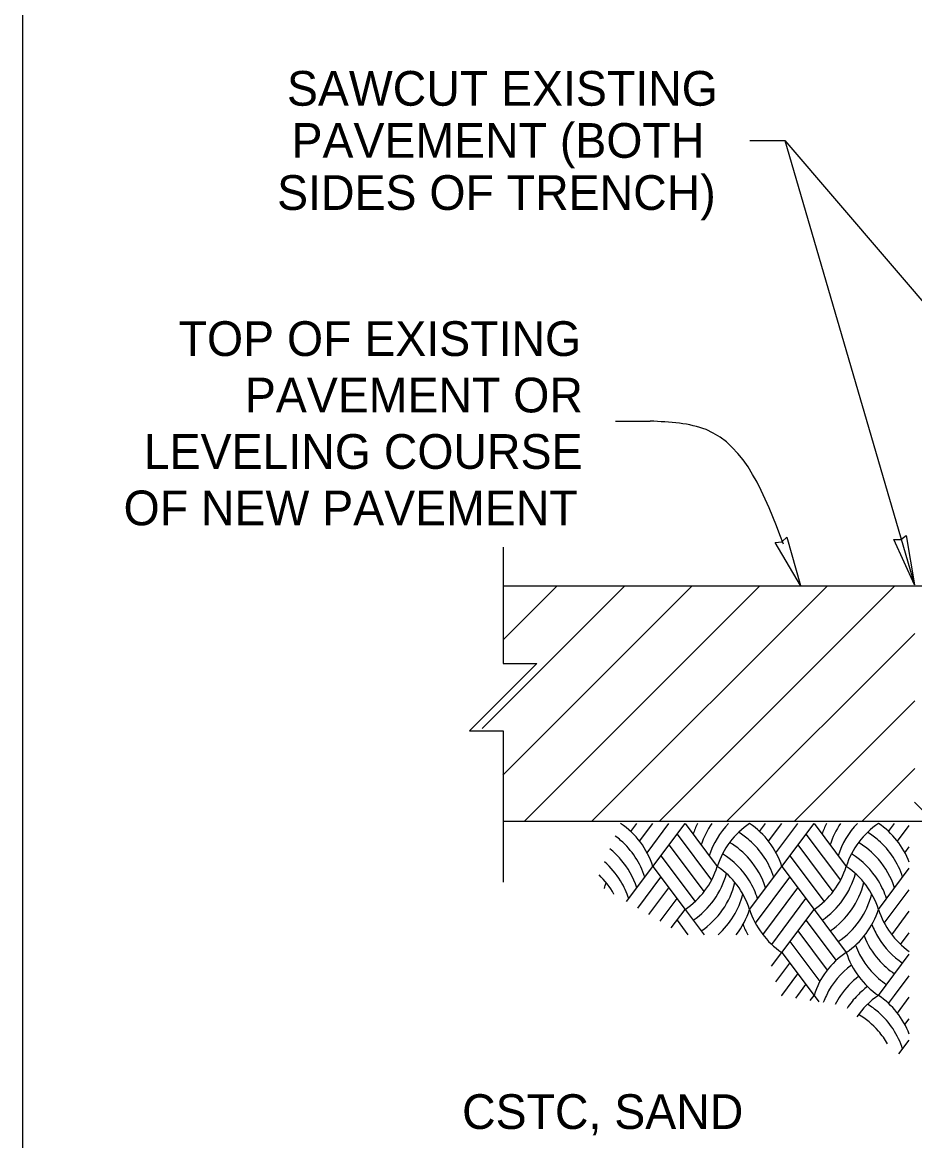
# Model space of a CAD drawing. Extents: x 99862 to 103151, y 100000 to 108153.
# Drawn here: x 99862 to 100273, y 100539 to 101054 of the extents above; entities that cross this region are included whole.
import ezdxf

# ---------------------------------------------------------------- set-up
doc = ezdxf.new("R2010")
doc.units = 0
for name, color, linetype in [('Level 1', 7, 'Continuous'), ('Level 10', 7, 'Continuous'), ('Level 15', 7, 'Continuous'), ('Level 18', 7, 'Continuous'), ('Level 20', 7, 'Continuous'), ('Level 27', 7, 'Continuous'), ('Level 60', 7, 'Continuous')]:
    doc.layers.add(name, color=color, linetype=linetype)

msp = doc.modelspace()

# ---------------------------------------------------------------- linework, layer by layer
at = {"layer": 'Level 1'}
msp.add_lwpolyline([(99862, 99999.5), (103151, 99999.5), (103151, 102075.5), (99862, 102075.5)], close=True, dxfattribs=at)
at = {"layer": 'Level 10'}
for points in [[(100406.95, 100794.33), (100083.51, 100794.33)], [(100582.64, 100685.87), (100083.51, 100685.87)]]:
    msp.add_lwpolyline(points, dxfattribs=at)
at = {"layer": 'Level 15'}
for p, q in [((100197.22, 100999.64), (100213.22, 100999.64)), ((100213.22, 100999.64), (100273.05, 100794.89)), ((100135.24, 100870.34), (100151.24, 100870.34))]:
    msp.add_line(p, q, dxfattribs=at)
for points in [[(100213.22, 100999.64), (100309.47, 100887.42)], [(100083.51, 100812.23), (100083.51, 100758.61), (100098.99, 100758.61), (100068.02, 100727.64), (100083.51, 100727.64), (100083.51, 100657.87)]]:
    msp.add_lwpolyline(points, dxfattribs=at)
for points in [[(100273.05, 100794.89), (100263.55, 100815.86), (100266.71, 100815.72), (100269.26, 100817.6)], [(100220.57, 100794.65), (100208.81, 100814.44), (100211.97, 100814.65), (100214.29, 100816.8)]]:
    msp.add_lwpolyline(points, close=True, dxfattribs=at)
msp.add_spline([(100212.64, 100813.62), (100177.01, 100866.4), (100151.24, 100870.34)], degree=3, dxfattribs=at)
at = {"layer": 'Level 27'}
msp.add_line((100280.56, 100687.2), (100272.99, 100694.77), dxfattribs=at)
at = {"layer": 'Level 60'}
for p, q in [((100073.79, 100728.73), (100139.39, 100794.33)), ((100083.35, 100707.18), (100170.51, 100794.33)), ((100083.51, 100769.56), (100108.28, 100794.33)), ((100093.16, 100685.87), (100201.62, 100794.33)), ((100124.27, 100685.87), (100232.73, 100794.33)), ((100155.38, 100685.87), (100263.84, 100794.33)), ((100186.49, 100685.87), (100273.15, 100772.53)), ((100217.61, 100685.87), (100273.15, 100741.41)), ((100248.72, 100685.87), (100273.15, 100710.3)), ((100142.3, 100681.27), (100145.07, 100684.96)), ((100146.37, 100676.81), (100152.49, 100684.96)), ((100149.82, 100671.5), (100159.92, 100684.96)), ((100152.49, 100665.17), (100167.34, 100684.96)), ((100167.34, 100684.96), (100182.19, 100665.17)), ((100201.69, 100681.27), (100204.46, 100684.96)), ((100205.77, 100676.81), (100211.89, 100684.96)), ((100209.21, 100671.5), (100219.31, 100684.96)), ((100211.89, 100665.17), (100226.74, 100684.96)), ((100226.74, 100684.96), (100241.59, 100665.17)), ((100261.09, 100681.27), (100263.86, 100684.96)), ((100265.17, 100676.81), (100270.63, 100684.09)), ((100163.63, 100680.01), (100179.52, 100658.83)), ((100223.03, 100680.01), (100238.91, 100658.83)), ((100159.92, 100675.07), (100176.07, 100653.52)), ((100219.31, 100675.07), (100235.47, 100653.52)), ((100268.61, 100671.5), (100270.63, 100674.19)), ((100156.2, 100670.12), (100172, 100649.06)), ((100215.6, 100670.12), (100231.39, 100649.06)), ((100140.38, 100649.02), (100152.49, 100665.17)), ((100152.49, 100665.17), (100167.34, 100645.37)), ((100197.04, 100645.37), (100211.89, 100665.17)), ((100211.89, 100665.17), (100226.74, 100645.37)), ((100256.44, 100645.37), (100270.63, 100664.29)), ((100145.53, 100645.99), (100156.2, 100660.22)), ((100199.71, 100639.03), (100215.6, 100660.22)), ((100150.69, 100642.96), (100159.92, 100655.27)), ((100203.16, 100633.72), (100219.31, 100655.27)), ((100259.11, 100639.03), (100270.63, 100654.39)), ((100155.85, 100639.94), (100163.63, 100650.32)), ((100207.23, 100629.26), (100223.03, 100650.32)), ((100161, 100636.91), (100167.34, 100645.37)), ((100167.34, 100645.37), (100176.09, 100633.7)), ((100211.89, 100625.57), (100226.74, 100645.37)), ((100226.74, 100645.37), (100241.59, 100625.57)), ((100262.55, 100633.72), (100270.63, 100644.49)), ((100163.63, 100640.42), (100168.67, 100633.7)), ((100223.03, 100640.42), (100236.93, 100621.87)), ((100219.31, 100635.47), (100232.86, 100617.41)), ((100266.63, 100629.26), (100270.63, 100634.59)), ((100215.6, 100630.52), (100229.41, 100612.1)), ((100207.1, 100619.18), (100211.89, 100625.57)), ((100211.89, 100625.57), (100226.74, 100605.77)), ((100256.44, 100605.77), (100270.63, 100624.69)), ((100209.1, 100611.95), (100215.6, 100620.62)), ((100211.89, 100605.77), (100219.31, 100615.67)), ((100263.86, 100605.77), (100270.63, 100614.79)), ((100219.31, 100605.77), (100223.03, 100610.72)), ((100211.76, 100605.6), (100211.89, 100605.77)), ((100218.38, 100604.53), (100219.31, 100605.77)), ((100225.01, 100603.46), (100226.74, 100605.77)), ((100226.74, 100605.77), (100228.95, 100602.83)), ((100261.09, 100602.07), (100263.86, 100605.77)), ((100265.17, 100597.61), (100270.63, 100604.89)), ((100268.61, 100592.3), (100270.63, 100594.99)), ((100265.89, 100578.78), (100270.63, 100585.09))]:
    msp.add_line(p, q, dxfattribs=at)
for centre, start, end in [((100116.68, 100653.78), 17.6434, 56.0957), ((100206.86, 100668.63), 154.2266, 162.3566), ((100210.58, 100663.68), 145.491, 162.3566), ((100214.29, 100658.73), 135.7127, 162.3566), ((100218, 100653.78), 123.9036, 162.3566), ((100176.08, 100653.78), 17.6434, 56.0963), ((100266.26, 100668.63), 154.2266, 162.3566), ((100269.97, 100663.68), 145.491, 162.3566), ((100273.68, 100658.73), 135.7127, 162.3566), ((100277.4, 100653.78), 123.9036, 162.3566), ((100235.47, 100653.78), 20.6916, 56.0963), ((100112.97, 100648.83), 48.9597, 53.7468), ((100172.37, 100648.83), 48.9597, 58.5465), ((100231.76, 100648.83), 48.9597, 58.5465), ((100109.26, 100643.88), 40.9413, 51.3732), ((100112.97, 100648.83), 17.6434, 48.9597), ((100168.66, 100643.88), 40.9413, 59.3021), ((100172.37, 100648.83), 17.6434, 48.9597), ((100228.05, 100643.88), 40.9413, 59.3021), ((100231.76, 100648.83), 17.6434, 48.9597), ((100109.26, 100643.88), 17.6434, 40.9414), ((100164.94, 100638.93), 31.3316, 58.4874), ((100168.65, 100643.88), 17.6434, 40.9414), ((100224.34, 100638.93), 31.3316, 58.4874), ((100228.05, 100643.88), 17.6434, 40.9414), ((100105.55, 100638.93), 31.3316, 48.9712), ((100146.38, 100676.55), 303.9036, 342.3566), ((100161.23, 100633.98), 17.6434, 56.0964), ((100205.78, 100676.55), 303.9036, 342.3566), ((100220.63, 100633.98), 17.6434, 56.0964), ((100101.83, 100633.98), 29.3994, 46.5357), ((100094.41, 100666.66), 341.9694, 346.3199), ((100105.55, 100638.93), 17.6434, 31.3317), ((100150.09, 100671.61), 303.9036, 345.0113), ((100153.81, 100666.66), 303.9036, 346.3199), ((100164.94, 100638.93), 17.6434, 31.3317), ((100209.49, 100671.61), 303.9036, 345.0113), ((100213.2, 100666.66), 303.9036, 346.3199), ((100224.34, 100638.93), 17.6434, 31.3317), ((100098.12, 100661.71), 345.7294, 345.7713), ((100157.52, 100661.71), 311.8163, 345.7713), ((100216.91, 100661.71), 303.9036, 345.7713), ((100161.23, 100656.76), 322.1523, 342.3566), ((100232.85, 100656.76), 197.6435, 236.0964), ((100220.63, 100656.76), 303.9036, 342.3566), ((100292.25, 100656.76), 197.6435, 234.8819), ((100229.14, 100651.81), 200.8778, 208.8059), ((100288.53, 100651.81), 200.8778, 211.332), ((100284.82, 100646.86), 201.4344, 220.9416), ((100288.53, 100651.81), 211.3319, 236.0964), ((100281.11, 100641.91), 200.2432, 228.9599), ((100262.55, 100594.38), 123.9036, 162.3566), ((100277.4, 100636.96), 197.6434, 236.0964), ((100284.82, 100646.86), 220.9415, 236.0964), ((100266.26, 100589.43), 126.3063, 154.2266), ((100269.97, 100584.48), 127.1006, 145.4911), ((100281.11, 100641.91), 228.9599, 236.0964), ((100273.68, 100579.53), 126.331, 135.7128), ((100266.26, 100589.43), 154.2265, 159.6619), ((100269.97, 100584.48), 145.491, 152.8911), ((100273.68, 100579.53), 135.7127, 147.4303), ((100277.4, 100574.58), 123.9036, 145.4797), ((100231.76, 100569.63), 48.9597, 58.5465), ((100235.47, 100574.58), 20.6916, 56.0963), ((100228.05, 100564.68), 40.9413, 59.3021), ((100231.76, 100569.63), 17.6434, 48.9597), ((100228.05, 100564.68), 29.8741, 40.9414)]:
    msp.add_arc(centre, 37.58, start, end, dxfattribs=at)

# ---------------------------------------------------------------- texts
at = {"layer": 'Level 18'}
for s, p in [('SAWCUT EXISTING', (99983.9, 101015.64)), ('PAVEMENT (BOTH ', (99986.01, 100991.64)), ('SIDES OF TRENCH)', (99979.38, 100967.64))]:
    msp.add_text(s, height=16, dxfattribs=at).set_placement(p)
at = {"layer": 'Level 20'}
for s, p in [('TOP OF EXISTING', (99933.99, 100900.34)), ('PAVEMENT OR', (99964.52, 100874.34)), ('LEVELING COURSE', (99917.94, 100848.34)), ('OF NEW PAVEMENT', (99908.63, 100822.34))]:
    msp.add_text(s, height=16, dxfattribs=at).set_placement(p)
msp.add_text('CSTC, SAND', height=16, rotation=360, dxfattribs=at).set_placement((100064.59, 100544.2))

doc.saveas('drawing.dxf')
